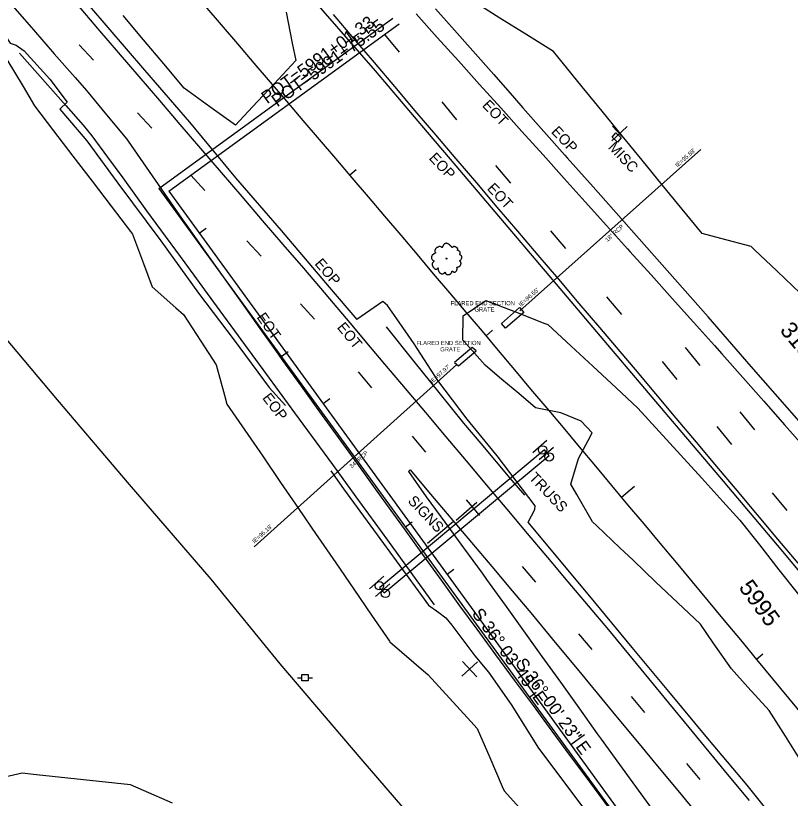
# Model space of a CAD drawing. Extents: x 2132221 to 2141942, y 535736 to 547298.
# Drawn here: x 2136476 to 2136843.6, y 542151 to 542522.3 of the extents above; entities that cross this region are included whole.
import ezdxf

# ---------------------------------------------------------------- set-up
doc = ezdxf.new("R2010")
doc.units = 0
for name, color, linetype in [('RD_EX_BldgApp', 7, 'Continuous'), ('RD_EX_BldgApp_txCode', 7, 'Continuous'), ('RD_EX_Conc', 7, 'Continuous'), ('RD_EX_DR_Inlet_txCode', 7, 'Continuous'), ('RD_EX_DR_Pipe', 7, 'Continuous'), ('RD_EX_DR_Pipe_txCode', 7, 'Continuous'), ('RD_EX_Fence_Other', 7, 'Continuous'), ('RD_EX_GuardRail', 7, 'Continuous'), ('RD_EX_Misc', 7, 'Continuous'), ('RD_EX_Misc_txCode', 7, 'Continuous'), ('RD_EX_Road', 7, 'Continuous'), ('RD_EX_Road_txCode', 7, 'Continuous'), ('RD_EX_UT', 7, 'Continuous'), ('RD_EX_VEG', 7, 'Continuous'), ('RD_HC_Cl', 7, 'Continuous'), ('RD_HC_Data', 7, 'Continuous'), ('RD_HC_Data_Tic', 7, 'Continuous'), ('RD_HC_TX_Sta50', 7, 'Continuous')]:
    doc.layers.add(name, color=color, linetype=linetype)

msp = doc.modelspace()

# ---------------------------------------------------------------- linework, layer by layer
at = {"layer": 'RD_EX_BldgApp'}
for p, q in [((2136728.12, 542320.78), (2136721.37, 542314.83)), ((2136731.24, 542317.47), (2136724.49, 542311.52)), ((2136694.85, 542291.28), (2136685.02, 542282.82)), ((2136683.73, 542282.27), (2136671.45, 542271.85)), ((2136650.67, 542256.35), (2136643.92, 542250.4)), ((2136653.49, 542252.72), (2136646.74, 542246.77))]:
    msp.add_line(p, q, dxfattribs=at)
msp.add_lwpolyline([(2136729.15, 542313.71), (2136727.01, 542316.36), (2136648.61, 542250.91), (2136650.8, 542248.46)], close=True, dxfattribs=at)
for centre in [(2136726.07, 542316.27), (2136729.19, 542312.97), (2136648.62, 542251.85), (2136651.44, 542248.22)]:
    msp.add_circle(centre, 2, dxfattribs=at)
at = {"layer": 'RD_EX_Conc'}
for points in [[(2136707.52, 542375.19), (2136706.54, 542376.32), (2136715.13, 542383.8), (2136716.12, 542382.67), (2136717.1, 542381.53), (2136708.51, 542374.06)], [(2136693.64, 542364.11), (2136692.7, 542364.87), (2136684.26, 542357.75), (2136685.2, 542356.99), (2136686.14, 542356.23), (2136694.57, 542363.35)]]:
    msp.add_lwpolyline(points, close=True, dxfattribs=at)
at = {"layer": 'RD_EX_DR_Pipe'}
for points in [[(2136715.32, 542382.33), (2136801.14, 542458.8)], [(2136685.37, 542356.81), (2136589.15, 542270.37)]]:
    msp.add_lwpolyline(points, dxfattribs=at)
at = {"layer": 'RD_EX_Fence_Other'}
for p, q in [((2136458.69, 542383.86), (2136495.62, 542340.06)), ((2136639.78, 542169.81), (2136676.71, 542127.08))]:
    msp.add_line(p, q, dxfattribs=at)
msp.add_lwpolyline([(2136495.62, 542340.06), (2136529.86, 542299.86), (2136568.67, 542254.9), (2136601.43, 542214.77), (2136639.78, 542169.81)], dxfattribs=at)
at = {"layer": 'RD_EX_GuardRail'}
for points in [[(2136477.88, 542504.45), (2136499.73, 542479.74), (2136508.1, 542470.37), (2136512.19, 542465.29), (2136519.64, 542455.2), (2136526.86, 542445.32), (2136538.1, 542429.77), (2136556.29, 542405.07), (2136571.12, 542384.64), (2136593.29, 542354.38), (2136608.35, 542333.89), (2136626.33, 542309.32), (2136637.39, 542294.07), (2136652.38, 542273.41), (2136674.68, 542242.76)], [(2136717.59, 542294.75), (2136710.73, 542302.92), (2136696.91, 542319.3), (2136688.73, 542329.03), (2136676.93, 542343.54), (2136665.16, 542358.23), (2136651.96, 542374.64)]]:
    msp.add_lwpolyline(points, dxfattribs=at)
at = {"layer": 'RD_EX_Misc'}
for p, q in [((2136651.04, 542513.4), (2136658.06, 542504.95)), ((2136506.19, 542508.41), (2136512.9, 542501.16)), ((2136678.2, 542481.4), (2136685.22, 542472.95)), ((2136533.83, 542476.18), (2136540.54, 542468.94)), ((2136758.98, 542462.86), (2136766.26, 542469.72)), ((2136759.19, 542469.93), (2136766.05, 542462.65)), ((2136703.77, 542451.22), (2136710.79, 542442.78)), ((2136559.08, 542446.67), (2136565.79, 542439.43)), ((2136729.83, 542420.26), (2136736.85, 542411.81)), ((2136585.73, 542415.47), (2136592.43, 542408.22)), ((2136756.45, 542388.95), (2136763.47, 542380.5)), ((2136611.12, 542385.57), (2136617.82, 542378.32)), ((2136793.66, 542364.82), (2136800.68, 542356.37)), ((2136782.8, 542358.16), (2136789.82, 542349.71)), ((2136638.54, 542353.25), (2136644.83, 542345.73)), ((2136819.65, 542334.32), (2136826.67, 542325.87)), ((2136808.73, 542327.32), (2136815.75, 542318.87)), ((2136664.22, 542322.75), (2136670.51, 542315.22)), ((2136834.93, 542295.93), (2136841.95, 542287.48)), ((2136689.78, 542292.63), (2136696.08, 542285.11)), ((2136716.37, 542261.02), (2136722.66, 542253.49)), ((2136743.07, 542229.09), (2136749.36, 542221.57)), ((2136687.8, 542208.88), (2136695.1, 542215.72)), ((2136688.03, 542215.95), (2136694.87, 542208.65)), ((2136768.08, 542199.29), (2136774.37, 542191.77)), ((2136794.39, 542167.5), (2136800.68, 542159.97))]:
    msp.add_line(p, q, dxfattribs=at)
for points in [[(2136474.63, 542526.84), (2136484.48, 542515.53), (2136494.32, 542504.21), (2136504.17, 542492.89), (2136509.54, 542486.72), (2136519.12, 542475.18), (2136528.71, 542463.64), (2136529.45, 542462.75), (2136537.98, 542450.41), (2136546.51, 542438.07), (2136555.04, 542425.73), (2136557.04, 542422.84), (2136565.74, 542410.62), (2136574.43, 542398.4), (2136583.13, 542386.17), (2136591.82, 542373.95), (2136600.51, 542361.73), (2136602.7, 542358.66), (2136611.48, 542346.5), (2136620.26, 542334.34), (2136629.05, 542322.18), (2136637.83, 542310.02), (2136646.61, 542297.86), (2136651.56, 542291.01), (2136660.35, 542278.85), (2136669.13, 542266.69), (2136677.92, 542254.53), (2136686.7, 542242.37), (2136694.79, 542231.18), (2136703.7, 542219.11), (2136712.62, 542207.05), (2136721.53, 542194.99), (2136730.44, 542182.92), (2136739.36, 542170.86), (2136748.27, 542158.8), (2136757.19, 542146.73)], [(2136505.14, 542527.65), (2136514.91, 542516.26), (2136524.68, 542504.88), (2136534.45, 542493.5), (2136544.21, 542482.11), (2136553.98, 542470.73), (2136563.75, 542459.35), (2136573.52, 542447.96), (2136583.28, 542436.58), (2136593.05, 542425.19), (2136602.82, 542413.81), (2136612.59, 542402.43), (2136622.35, 542391.04), (2136624.96, 542388.01), (2136634.62, 542376.54), (2136644.29, 542365.07), (2136651.11, 542356.97), (2136660.77, 542345.5), (2136670.44, 542334.03), (2136680.1, 542322.56), (2136689.77, 542311.09), (2136699.43, 542299.62), (2136709.1, 542288.14), (2136718.76, 542276.67), (2136728.43, 542265.2), (2136738.09, 542253.73), (2136747.76, 542242.26), (2136757.28, 542230.96), (2136766.81, 542219.38), (2136776.35, 542207.81), (2136785.88, 542196.23), (2136795.42, 542184.65), (2136804.96, 542173.07), (2136814.49, 542161.49), (2136824.03, 542149.91)], [(2136626.62, 542522.89), (2136636.34, 542511.47), (2136646.06, 542500.05), (2136655.78, 542488.62), (2136665.5, 542477.2), (2136675.22, 542465.78), (2136684.94, 542454.35), (2136694.67, 542442.93), (2136704.39, 542431.5), (2136714.11, 542420.08), (2136723.83, 542408.66), (2136733.55, 542397.23), (2136743.27, 542385.81), (2136752.99, 542374.38), (2136762.71, 542362.96), (2136770, 542354.4), (2136779.64, 542342.91), (2136789.29, 542331.42), (2136798.93, 542319.93), (2136808.58, 542308.44), (2136818.22, 542296.96), (2136827.87, 542285.47), (2136837.51, 542273.98), (2136847.16, 542262.49)], [(2136666.07, 542523.16), (2136676.1, 542512), (2136686.14, 542500.85), (2136696.17, 542489.7), (2136706.2, 542478.55), (2136716.23, 542467.4), (2136726.27, 542456.25), (2136736.3, 542445.1), (2136746.33, 542433.95), (2136756.36, 542422.79), (2136766.4, 542411.64), (2136767.5, 542410.42), (2136777.53, 542399.27), (2136787.56, 542388.11), (2136797.6, 542376.96), (2136807.63, 542365.81), (2136811.14, 542361.91), (2136821.07, 542350.67), (2136831, 542339.42), (2136840.93, 542328.18), (2136850.86, 542316.94)], [(2136662.45, 542306.02), (2136663.23, 542306.78), (2136672.9, 542295.31), (2136682.57, 542283.84), (2136692.24, 542272.37), (2136701.91, 542260.91), (2136711.58, 542249.44), (2136721.24, 542237.97), (2136723.27, 542235.57), (2136732.83, 542224.01), (2136742.39, 542212.45), (2136751.95, 542200.89), (2136761.51, 542189.33), (2136771.07, 542177.77), (2136780.63, 542166.21), (2136790.19, 542154.66), (2136799.75, 542143.1)], [(2136662.45, 542306.02), (2136670.8, 542294.09), (2136679.65, 542281.97), (2136688.49, 542269.86), (2136697.34, 542257.75), (2136699.51, 542254.78), (2136708.25, 542242.6), (2136717, 542230.41), (2136725.75, 542218.23), (2136734.49, 542206.04), (2136743.24, 542193.86), (2136751.99, 542181.67), (2136753.81, 542179.12), (2136762.62, 542166.98), (2136771.42, 542154.83), (2136780.22, 542142.69)]]:
    msp.add_lwpolyline(points, dxfattribs=at)
msp.add_lwpolyline([(2136760.87, 542466.69), (2136763.39, 542464.33), (2136761.54, 542462.36), (2136759.03, 542464.73)], close=True, dxfattribs=at)
at = {"layer": 'RD_EX_Road'}
for points in [[(2136210.45, 542994.01), (2136234.22, 542968.05), (2136257.92, 542941.67), (2136282.25, 542914.72), (2136308.7, 542884.94), (2136331.8, 542859.31), (2136354.58, 542833.7), (2136377.43, 542807.83), (2136400.08, 542782.32), (2136427.74, 542750.46), (2136454.44, 542719.62), (2136474.96, 542695.67), (2136499.05, 542667.83), (2136523.33, 542639.75), (2136553.86, 542604.19), (2136573.33, 542581.21), (2136595.44, 542555.48), (2136621.73, 542524.58), (2136646.55, 542496.07), (2136671.24, 542467.02), (2136682.24, 542454.15), (2136707.76, 542424.02)], [(2136152.96, 542932.59), (2136173.61, 542909.88), (2136199.52, 542880.76), (2136226.67, 542850.63), (2136257.39, 542816.27), (2136281.22, 542789.5), (2136310.73, 542756.07), (2136337.5, 542725.99), (2136361.31, 542699.01), (2136385.33, 542671.99), (2136411.17, 542642.21), (2136438.34, 542611.01), (2136458.33, 542587.63), (2136482.4, 542559.87), (2136511.06, 542526.75), (2136537.12, 542496.38), (2136558.42, 542471.71), (2136580.29, 542445.43), (2136602.04, 542420.39), (2136624.83, 542393.43), (2136637.86, 542378.13)], [(2136125.68, 542907.79), (2136146.36, 542885.11), (2136169.87, 542858.93), (2136192.85, 542833.18), (2136219.09, 542804), (2136241.29, 542778.73), (2136263.5, 542753.94), (2136282.27, 542732.64), (2136304.98, 542706.91), (2136329.99, 542678.45), (2136352.51, 542652.49), (2136370.6, 542631.96), (2136395.45, 542603.48), (2136419.14, 542576.02), (2136437.94, 542554.74), (2136458.72, 542530.57), (2136471.71, 542516.25), (2136471.35, 542512.41), (2136473.35, 542509.2), (2136476.17, 542508.29), (2136479.99, 542505.58), (2136492.25, 542492.13), (2136500.39, 542481.29)], [(2136675.19, 542525.56), (2136683.03, 542516.86), (2136692.94, 542505.6), (2136702.85, 542494.34), (2136712.77, 542483.08), (2136716.75, 542478.56), (2136726.7, 542467.33), (2136736.64, 542456.1), (2136737.67, 542454.93)], [(2136500.39, 542481.29), (2136497.01, 542477.92), (2136509.73, 542462.89), (2136524.53, 542442.87), (2136544.85, 542415.44), (2136562.73, 542390.64), (2136579.64, 542368.29), (2136596.29, 542345.95), (2136604.1, 542337.4)], [(2137018.27, 542136.37), (2137005.48, 542151.45), (2136975.87, 542184.99), (2136947.77, 542216.65), (2136939.95, 542224.86), (2136938.77, 542225.47), (2136924.87, 542241.7), (2136899.92, 542270.58), (2136876.91, 542296.83), (2136853.51, 542323.4), (2136825.04, 542355.91), (2136804.58, 542379.43), (2136770.65, 542417.8), (2136750.04, 542441.13), (2136737.67, 542454.93)], [(2136707.76, 542424.02), (2136729, 542399.05), (2136756.88, 542366.08), (2136784.05, 542334.02), (2136809.93, 542303.58), (2136839.08, 542269.1), (2136860.77, 542243.12), (2136882.71, 542216.67), (2136907.37, 542186.91), (2136924.47, 542166.25), (2136945.23, 542140.83), (2136969.19, 542111.86), (2136995.45, 542079.97), (2137017.76, 542052.48), (2137039.43, 542026.33), (2137063.92, 541996), (2137080.05, 541976.19), (2137096.8, 541955.76), (2137112.6, 541936.21), (2137134.84, 541908.64), (2137151.98, 541887.74), (2137171.65, 541863.54), (2137193.35, 541837.19)], [(2136841.62, 542134.18), (2136823.08, 542157.17), (2136804.42, 542179.3), (2136785.99, 542201.74), (2136768.57, 542222.52), (2136748.46, 542246.92), (2136731.67, 542267.03), (2136719.24, 542282.03), (2136722.31, 542287.99), (2136722.51, 542289.76), (2136704.52, 542313.5), (2136690.21, 542330.92), (2136676.31, 542349.28), (2136665.18, 542366.55), (2136656.94, 542378.54), (2136652.49, 542384.87), (2136650.17, 542386.77), (2136637.86, 542378.13)], [(2136625.53, 542306.39), (2136631.5, 542297.86), (2136650.58, 542271.95), (2136668.52, 542247.25), (2136671.86, 542242.66), (2136676.87, 542239.08), (2136680.1, 542236.56), (2136683.03, 542233.17), (2136693.94, 542218.56), (2136700.43, 542210.84), (2136711.12, 542195.43), (2136724.17, 542174.8), (2136731.92, 542164.44), (2136749.24, 542141.25)]]:
    msp.add_lwpolyline(points, dxfattribs=at)
at = {"layer": 'RD_EX_UT'}
for p, q in [((2136609.72, 542208.14), (2136611.78, 542208.14)), ((2136609.72, 542208.14), (2136611.78, 542208.14)), ((2136609.72, 542208.13), (2136611.78, 542208.13)), ((2136613.28, 542208.18), (2136613.28, 542208.18)), ((2136613.28, 542208.18), (2136613.28, 542208.18)), ((2136613.28, 542208.17), (2136613.28, 542208.17)), ((2136614.78, 542208.14), (2136616.92, 542208.14)), ((2136614.78, 542208.14), (2136616.92, 542208.14)), ((2136614.78, 542208.13), (2136616.92, 542208.13))]:
    msp.add_line(p, q, dxfattribs=at)
for points in [[(2136611.78, 542206.68), (2136611.78, 542209.68), (2136614.78, 542209.68), (2136614.78, 542206.68)], [(2136611.78, 542206.68), (2136611.78, 542209.68), (2136614.78, 542209.68), (2136614.78, 542206.68)], [(2136611.78, 542206.67), (2136611.78, 542209.67), (2136614.78, 542209.67), (2136614.78, 542206.67)]]:
    msp.add_lwpolyline(points, close=True, dxfattribs=at)
at = {"layer": 'RD_EX_VEG'}
for points in [[(2136848.25, 542390.69), (2136837.39, 542401.04), (2136826.53, 542411.38), (2136825.1, 542412.75), (2136810.6, 542416.58), (2136801.86, 542418.9), (2136792.37, 542430.51), (2136782.87, 542442.12), (2136773.38, 542453.73), (2136763.88, 542465.34), (2136754.38, 542476.95), (2136744.89, 542488.56), (2136735.39, 542500.18), (2136731.24, 542505.25), (2136718.53, 542513.21), (2136705.82, 542521.17), (2136693.1, 542529.14)], [(2136604.34, 542523.98), (2136607.26, 542509.27), (2136608.89, 542501.02), (2136598.68, 542490.03), (2136588.46, 542479.05), (2136580.31, 542470.29), (2136568.17, 542479.09), (2136556.01, 542487.92), (2136546.37, 542499.41), (2136536.73, 542510.9), (2136527.08, 542522.39)], [(2136471.79, 542501.52), (2136479.48, 542488.64), (2136484.91, 542479.53), (2136494.02, 542467.61), (2136503.13, 542455.69), (2136512.24, 542443.77), (2136521.34, 542431.86), (2136530.45, 542419.94), (2136531.39, 542418.71), (2136536.62, 542404.65), (2136540.74, 542393.59), (2136552.02, 542383.71), (2136555.69, 542380.5), (2136563.88, 542367.93), (2136571.19, 542356.71), (2136575.11, 542342.24), (2136576.26, 542338.01), (2136584.74, 542325.64), (2136593.23, 542313.27), (2136601.71, 542300.9), (2136610.19, 542288.53), (2136618.68, 542276.16), (2136619.46, 542275.01), (2136627.95, 542262.64), (2136636.43, 542250.27), (2136644.91, 542237.9), (2136653.4, 542225.53), (2136653.61, 542225.21), (2136664.98, 542215.43), (2136671.81, 542209.54), (2136681.94, 542198.48), (2136692.07, 542187.41), (2136695.05, 542184.16), (2136701, 542170.39), (2136706.95, 542156.62), (2136707.87, 542154.5), (2136717.87, 542143.31)], [(2136849.29, 542167.82), (2136841.28, 542180.51), (2136833.58, 542192.71), (2136823.49, 542203.81), (2136815.64, 542212.45), (2136807.07, 542224.76), (2136800.95, 542233.56), (2136790.07, 542243.89), (2136779.85, 542253.6), (2136768.97, 542263.93), (2136762.7, 542269.89), (2136751.82, 542280.22), (2136749.81, 542282.12), (2136742.36, 542295.14), (2136739.51, 542300.1), (2136743.1, 542312.2), (2136747.68, 542320.75), (2136749.63, 542324.39), (2136744.32, 542329.91), (2136734.71, 542333.88), (2136722.65, 542336.32), (2136714.71, 542343.04), (2136706.78, 542349.76), (2136698.84, 542356.48), (2136688.82, 542367.65), (2136688.16, 542368.39), (2136688.31, 542379.84), (2136699.18, 542387.21), (2136713.15, 542381.75), (2136727.12, 542376.28), (2136728.56, 542375.72), (2136739.57, 542365.53), (2136749.93, 542355.94), (2136760.94, 542345.76), (2136771.3, 542336.17), (2136781.39, 542325.07), (2136791.48, 542313.97), (2136801.57, 542302.87), (2136811.66, 542291.77), (2136819.64, 542282.99), (2136828.93, 542271.21), (2136838.21, 542259.43), (2136847.49, 542247.65)], [(2136550.37, 542148.67), (2136536.63, 542154.68), (2136530.55, 542157.34), (2136515.64, 542158.97), (2136500.73, 542160.6), (2136485.82, 542162.22), (2136479.14, 542162.95), (2136464.5, 542159.67), (2136449.87, 542156.38), (2136435.23, 542153.09), (2136433.33, 542152.67), (2136422.73, 542142.06)]]:
    msp.add_lwpolyline(points, dxfattribs=at)
for centre, radius in [((2136680.43, 542407.07), 0.25), ((2136680.4, 542407.07), 0.0001)]:
    msp.add_circle(centre, radius, dxfattribs=at)
for points in [[(2136685.73, 542411.89), (2136685.54, 542412.13), (2136685.25, 542412.29), (2136685, 542412.41), (2136684.8, 542412.52), (2136684.57, 542412.61), (2136684.24, 542412.71), (2136683.94, 542412.74), (2136683.67, 542412.66), (2136683.47, 542412.54), (2136683.24, 542412.39), (2136683.11, 542412.27), (2136683, 542412.34), (2136682.92, 542412.47), (2136682.8, 542412.7), (2136682.63, 542412.88), (2136682.46, 542413.06), (2136682.2, 542413.3), (2136681.96, 542413.56), (2136681.74, 542413.72), (2136681.48, 542413.92), (2136681.13, 542414.11), (2136680.8, 542414.28), (2136680.41, 542414.33), (2136679.89, 542414.18), (2136679.55, 542414.03), (2136679.27, 542413.97), (2136679.05, 542413.55), (2136678.91, 542413.19), (2136678.78, 542413.03), (2136678.52, 542412.69), (2136678.43, 542412.46), (2136678.37, 542412.23), (2136678.3, 542412.27), (2136678.01, 542412.51), (2136677.73, 542412.66), (2136677.27, 542412.81), (2136676.96, 542412.82), (2136676.65, 542412.67), (2136676.38, 542412.45), (2136676.16, 542412.38), (2136675.91, 542412.25), (2136675.84, 542412.22), (2136675.57, 542412.03), (2136675.31, 542411.65), (2136675.07, 542411.39), (2136675, 542411.14), (2136674.97, 542410.92), (2136674.91, 542410.62), (2136675.02, 542410.17), (2136675.17, 542409.87), (2136675.29, 542409.7), (2136674.81, 542409.49), (2136674.52, 542409.28), (2136674.14, 542409.1), (2136674.09, 542409.05), (2136673.71, 542408.76), (2136673.57, 542408.43), (2136673.35, 542408.12), (2136673.31, 542407.84), (2136673.28, 542407.43), (2136673.34, 542407.04), (2136673.59, 542406.59), (2136673.88, 542406.32), (2136674.4, 542406.02), (2136674.63, 542405.89), (2136674.49, 542405.79), (2136674.23, 542405.51), (2136673.92, 542405.22), (2136673.79, 542404.89), (2136673.66, 542404.63), (2136673.58, 542404.35), (2136673.64, 542403.95), (2136673.86, 542403.61), (2136674.04, 542403.2), (2136674.29, 542402.82), (2136674.62, 542402.44), (2136675.14, 542402.11), (2136675.42, 542401.99), (2136675.61, 542402.04), (2136676.02, 542402.15), (2136676.15, 542402.34), (2136676.61, 542402.74), (2136676.55, 542402.54), (2136676.41, 542402.18), (2136676.54, 542401.61), (2136676.68, 542401.2), (2136676.9, 542400.75), (2136677.05, 542400.48), (2136677.43, 542400.18), (2136677.74, 542399.96), (2136678.09, 542399.78), (2136678.5, 542399.75), (2136678.82, 542399.81), (2136679.05, 542399.96), (2136679.38, 542400.16), (2136679.54, 542400.25)], [(2136679.54, 542400.25), (2136679.61, 542400.42), (2136679.76, 542400.63), (2136679.79, 542400.56), (2136679.88, 542400.39), (2136679.98, 542400.11), (2136680.08, 542399.89), (2136680.32, 542399.67), (2136680.58, 542399.54), (2136681.09, 542399.4), (2136681.62, 542399.53), (2136682.1, 542399.6), (2136682.39, 542399.77), (2136682.52, 542399.96), (2136682.86, 542400.32), (2136682.91, 542400.64), (2136682.96, 542400.76), (2136683.19, 542401.11), (2136683.27, 542401.09), (2136683.5, 542400.92), (2136683.85, 542400.74), (2136684.13, 542400.62), (2136684.41, 542400.58), (2136684.62, 542400.68), (2136684.9, 542400.97), (2136685.22, 542401.21), (2136685.28, 542401.37), (2136685.32, 542401.54), (2136685.42, 542401.73), (2136685.42, 542401.95), (2136685.46, 542402.12), (2136685.47, 542402.26), (2136685.49, 542402.46), (2136685.46, 542402.67), (2136685.39, 542402.81), (2136685.47, 542402.95), (2136685.72, 542402.98), (2136685.82, 542403.01), (2136686, 542403.15), (2136686.41, 542403.23), (2136686.74, 542403.46), (2136687.01, 542403.79), (2136687.18, 542404.02), (2136687.28, 542404.31), (2136687.32, 542404.63), (2136687.36, 542404.84), (2136687.33, 542405.05), (2136687.2, 542405.38), (2136687.07, 542405.59), (2136686.83, 542405.85), (2136686.73, 542406.03), (2136686.78, 542406.04), (2136686.89, 542406.15), (2136687.09, 542406.33), (2136687.36, 542406.7), (2136687.63, 542407.15), (2136687.64, 542407.17), (2136687.76, 542407.41), (2136687.75, 542407.71), (2136687.7, 542407.91), (2136687.65, 542408.14), (2136687.5, 542408.34), (2136687.3, 542408.56), (2136687.07, 542408.72), (2136686.86, 542408.8), (2136686.65, 542408.84), (2136686.71, 542409), (2136686.86, 542409.28), (2136686.93, 542409.42), (2136686.96, 542409.64), (2136686.95, 542409.94), (2136686.73, 542410.36), (2136686.25, 542410.76), (2136685.9, 542410.84), (2136685.66, 542410.83), (2136685.72, 542410.95), (2136685.73, 542411.24), (2136685.79, 542411.43), (2136685.76, 542411.64), (2136685.73, 542411.82), (2136685.7, 542411.93)]]:
    msp.add_spline(points, degree=3, dxfattribs=at)
at = {"layer": 'RD_HC_Cl'}
for p, q in [((2136543.98, 542440.37), (2136874.2, 541986.92)), ((2136548.76, 542438.96), (2136910.69, 541940.92))]:
    msp.add_line(p, q, dxfattribs=at)
msp.add_arc((2118950.8, 527389.88), 23225.51, 39.112741, 42.881786, dxfattribs=at)
at = {"layer": 'RD_HC_Data'}
for p, q in [((2136543.98, 542440.37), (2136654.95, 542521.18)), ((2136543.98, 542440.37), (2136654.95, 542521.18)), ((2136548.76, 542438.96), (2136658.06, 542518.39))]:
    msp.add_line(p, q, dxfattribs=at)
at = {"layer": 'RD_HC_Data_Tic'}
for p, q in [((2136634.57, 542446.72), (2136637.61, 542449.31)), ((2136563.13, 542419.18), (2136566.37, 542421.54)), ((2136699.23, 542370.44), (2136702.29, 542373.02)), ((2136602.07, 542360.61), (2136605.3, 542362.97)), ((2136602.07, 542360.61), (2136605.3, 542362.97)), ((2136621.92, 542338.29), (2136625.15, 542340.64)), ((2136763.57, 542293.88), (2136769.7, 542299.02)), ((2136660.93, 542279.77), (2136664.17, 542282.13)), ((2136660.93, 542279.77), (2136664.17, 542282.13)), ((2136680.7, 542257.39), (2136683.94, 542259.75)), ((2136827.57, 542217.05), (2136830.65, 542219.6)), ((2136719.8, 542198.94), (2136723.03, 542201.29)), ((2136719.8, 542198.94), (2136723.03, 542201.29)), ((2136739.49, 542176.5), (2136745.96, 542181.2))]:
    msp.add_line(p, q, dxfattribs=at)

# ---------------------------------------------------------------- texts
at = {"layer": 'RD_EX_BldgApp_txCode'}
for s, p in [('TRUSS', (2136719.24, 542302.78)), ('SIGNS', (2136661.76, 542291.82))]:
    msp.add_text(s, height=5, rotation=313.3162, dxfattribs=at).set_placement(p)
at = {"layer": 'RD_EX_DR_Inlet_txCode'}
for s, rotation, p in [("IE=95.88'", 41.7037, (2136790.05, 542450.26)), ("IE=96.55'", 41.7037, (2136715.77, 542384.08)), ("IE=97.97'", 41.932, (2136673.68, 542347.65)), ("IE=96.18'", 41.932, (2136589.3, 542271.86))]:
    msp.add_text(s, height=2, rotation=rotation, dxfattribs=at).set_placement(p)
for s, p in [('FLARED END SECTION', (2136682.4, 542384.91)), ('GRATE', (2136693.73, 542381.91)), ('FLARED END SECTION', (2136666.15, 542366.03)), ('GRATE', (2136677.48, 542363.03))]:
    msp.add_text(s, height=2, dxfattribs=at).set_placement(p)
at = {"layer": 'RD_EX_DR_Pipe_txCode'}
for s, rotation, p in [('18" RCP', 41.7037, (2136756.8, 542414.85)), ('24" RCP', 41.932, (2136635.53, 542307.43))]:
    msp.add_text(s, height=2, rotation=rotation, dxfattribs=at).set_placement(p)
at = {"layer": 'RD_EX_Misc_txCode'}
for s, rotation, p in [('EOT', 313.3162, (2136697.1, 542479.52)), (' MISC', 313.3162, (2136755.57, 542460.94)), ('EOT', 313.3162, (2136699.41, 542440.08)), ('EOT', 305.0292, (2136590.17, 542379.23)), ('EOT', 309.4716, (2136628.25, 542374.3))]:
    msp.add_text(s, height=5, rotation=rotation, dxfattribs=at).set_placement(p)
at = {"layer": 'RD_EX_Road_txCode'}
for rotation, p in [(313.3162, (2136729.85, 542467.01)), (313.3162, (2136671.81, 542454.46)), (310.4805, (2136617.63, 542404.51)), (307.4569, (2136592.83, 542340.89))]:
    msp.add_text('EOP', height=5, rotation=rotation, dxfattribs=at).set_placement(p)
at = {"layer": 'RD_HC_Data'}
for s, rotation, p in [('POT=5991+01.33', 36.0625, (2136595.35, 542480.25)), ('POT=5991+01.33', 36.0625, (2136595.35, 542480.25)), ('POT=5991+75.55', 36.0063, (2136600.16, 542478.79)), ('S 36%%d 03\' 45" E', 306.0625, (2136692.23, 542238.5)), ('S 36%%d 00\' 23" E', 306.0063, (2136712.86, 542214.85))]:
    msp.add_text(s, height=6, rotation=rotation, dxfattribs=at).set_placement(p)
at = {"layer": 'RD_HC_TX_Sta50'}
for s, rotation, p in [('3185', 309.9193, (2136838.3, 542372.87)), ('5995', 306.0063, (2136818.85, 542251.01))]:
    msp.add_text(s, height=8, rotation=rotation, dxfattribs=at).set_placement(p)

doc.saveas('drawing.dxf')
